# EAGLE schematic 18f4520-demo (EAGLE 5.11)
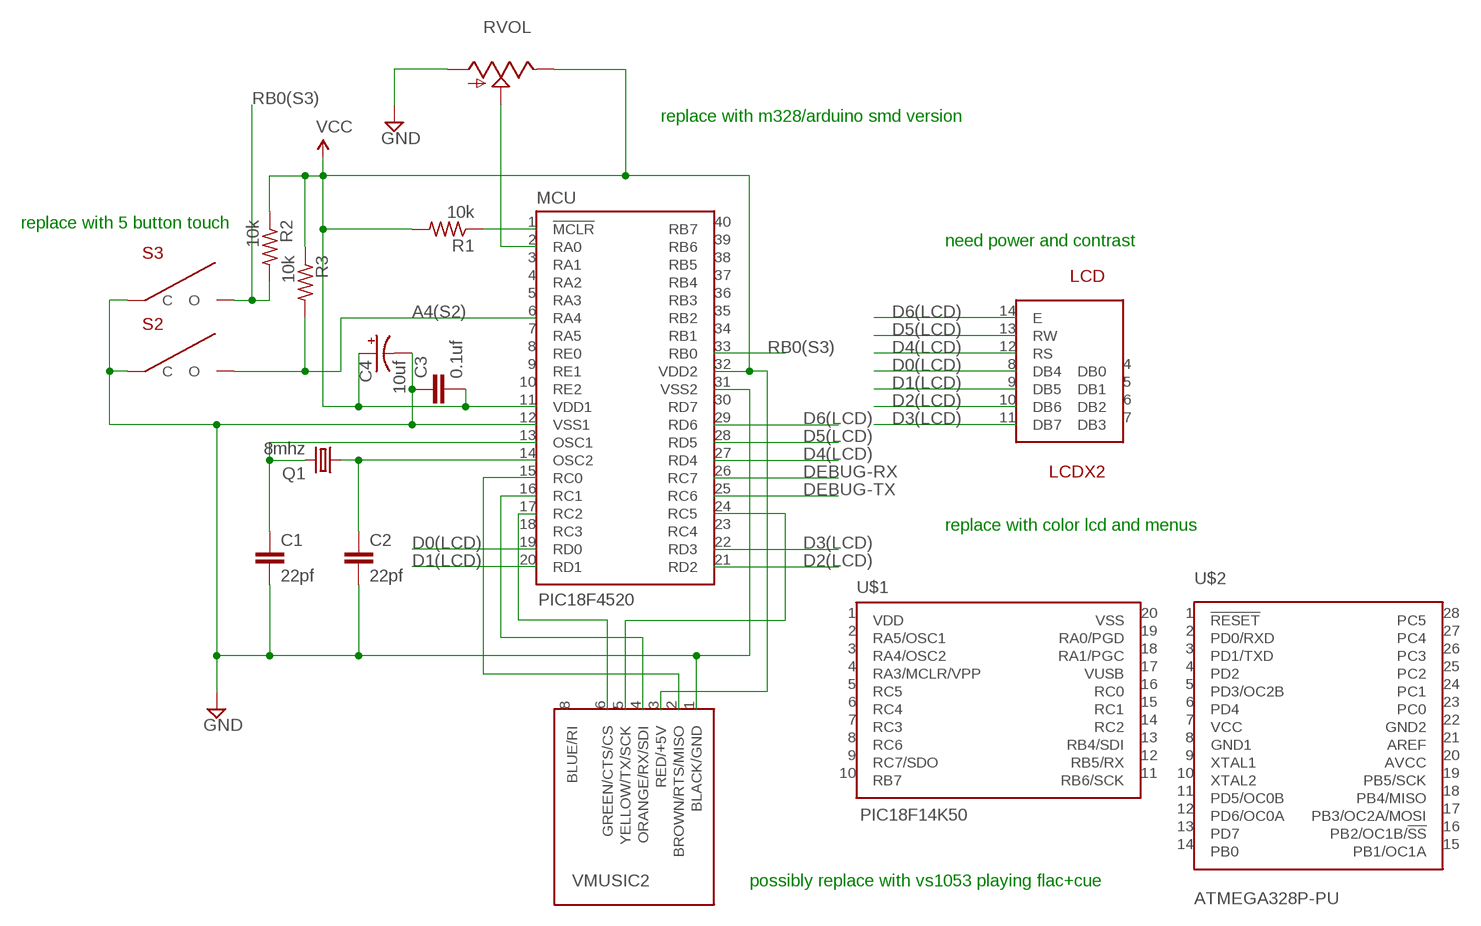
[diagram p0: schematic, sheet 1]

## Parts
C1  22pf  C-EU050-024X044  [C050-024X044]
C2  22pf  C-EU050-024X044  [C050-024X044]
C3  0.1uf  C-EU050-024X044  [C050-024X044]
C4  10uf  CPOL-USE2-4  [E2-4]
LCD  LCDX2  [7X2]
MCU  PIC18F4520  [DIL40-6]
Q1  8mhz  CRYSTALHC49U-V  [HC49U-V]
R1  10k  R-US_0411/12  [0411/12]
R2  10k  R-US_0411/12  [0411/12]
R3  10k  R-US_0411/12  [0411/12]
RVOL  POT-TRIM-PARALLAX  [POT-TRIM-PARALLAX]
S2  SWITCH-SPST  [2SIL-0.1IN]
S3  SWITCH-SPST  [2SIL-0.1IN]
U$1  PIC18F14K50  [DIL20]
U$2  ATMEGA328P-PU  [DIL28-3]
VMUSIC2  VMUSIC2  [VMUSIC2]

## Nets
A4(S2): MCU.6(RA4) R3.2 S2.2(O)
D0(LCD): LCD.8(DB4) MCU.19(RD0)
D1(LCD): LCD.9(DB5) MCU.20(RD1)
D2(LCD): LCD.10(DB6) MCU.21(RD2)
D3(LCD): LCD.11(DB7) MCU.22(RD3)
D4(LCD): LCD.12(RS) MCU.27(RD4)
D5(LCD): LCD.13(RW) MCU.28(RD5)
D6(LCD): LCD.14(E) MCU.29(RD6)
DEBUG-RX: MCU.26(RC7)
DEBUG-TX: MCU.25(RC6)
GND: C1.2 C2.2 C3.1 C4.- MCU.12(VSS1) MCU.31(VSS2) RVOL.1(A) S2.1(C) S3.1(C) VMUSIC2.1(BLACK/GND)
N$1: MCU.1(!MCLR) R1.1
N$2: C2.1 MCU.14(OSC2) Q1.1
N$3: C1.1 MCU.13(OSC1) Q1.2
N$5: MCU.16(RC1) VMUSIC2.4(ORANGE/RX/SDI)
N$6: MCU.15(RC0) VMUSIC2.2(BROWN/RTS/MISO)
N$7: MCU.24(RC5) VMUSIC2.5(YELLOW/TX/SCK)
N$8: MCU.17(RC2) VMUSIC2.6(GREEN/CTS/CS)
N$10: MCU.2(RA0) RVOL.2(S)
RB0(S3): MCU.33(RB0) R2.2 S3.2(O)
VCC: C3.2 C4.+ MCU.11(VDD1) MCU.32(VDD2) R1.2 R2.1 R3.1 RVOL.3(E) VMUSIC2.3(RED/+5V)
Unconnected: LCD.4(DB0) LCD.5(DB1) LCD.6(DB2) LCD.7(DB3) MCU.3(RA1) MCU.4(RA2) MCU.5(RA3) MCU.7(RA5) MCU.8(RE0) MCU.9(RE1) MCU.10(RE2) MCU.18(RC3) MCU.23(RC4) MCU.30(RD7) MCU.34(RB1) MCU.35(RB2) MCU.36(RB3) MCU.37(RB4) MCU.38(RB5) MCU.39(RB6) MCU.40(RB7) U$1.1(VDD) U$1.2(RA5/OSC1) U$1.3(RA4/OSC2) U$1.4(RA3/MCLR/VPP) U$1.5(RC5) U$1.6(RC4) U$1.7(RC3) U$1.8(RC6) U$1.9(RC7/SDO) U$1.10(RB7) U$1.11(RB6/SCK) U$1.12(RB5/RX) U$1.13(RB4/SDI) U$1.14(RC2) U$1.15(RC1) U$1.16(RC0) U$1.17(VUSB) U$1.18(RA1/PGC) U$1.19(RA0/PGD) U$1.20(VSS) U$2.1(!RESET) U$2.2(PD0/RXD) U$2.3(PD1/TXD) U$2.4(PD2) U$2.5(PD3/OC2B) U$2.6(PD4) U$2.7(VCC) U$2.8(GND1) U$2.9(XTAL1) U$2.10(XTAL2) U$2.11(PD5/OC0B) U$2.12(PD6/OC0A) U$2.13(PD7) U$2.14(PB0) U$2.15(PB1/OC1A) U$2.16(PB2/OC1B/!SS) U$2.17(PB3/OC2A/MOSI) U$2.18(PB4/MISO) U$2.19(PB5/SCK) U$2.20(AVCC) U$2.21(AREF) U$2.22(GND2) U$2.23(PC0) U$2.24(PC1) U$2.25(PC2) U$2.26(PC3) U$2.27(PC4) U$2.28(PC5) VMUSIC2.8(BLUE/RI)

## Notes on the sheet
- replace with m328/arduino smd version
- replace with 5 button touch
- need power and contrast
- replace with color lcd and menus
- possibly replace with vs1053 playing flac+cue

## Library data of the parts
C1-C3 = rcl:C-EU: CAPACITOR, European symbol
C4 = rcl:CPOL-US: POLARIZED CAPACITOR, American symbol
LCD = trl:LCDX2
MCU = trl:PIC18F4520
Q1 = crystal:CRYSTAL: CRYSTAL; OC_FARNELL: 1666969; OC_NEWARK: unknown
R1-R3 = resistor:R-US_: RESISTOR, American symbol
RVOL = trl:POT-TRIM-PARALLAX: POTENTIOMETER
S2 S3 = trl:SWITCH-SPST
U$1 = trl:PIC18F14K50
U$2 = trl:ATMEGA328P-PU
VMUSIC2 = trl:VMUSIC2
